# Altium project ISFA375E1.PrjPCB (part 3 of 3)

## Sheet ISFA375_REDRIVER_TUSB1044.SchDoc
size 431 x 279 mm; Date: Not shown in title block; ApprovedBy: Not shown in title block; CheckedBy: Not shown in title block; Author: Not shown in title block; CompanyName: Not shown in title block; DrawnBy: Thomas Mauer; Engineer: Not shown in title block; Organization: Not shown in title block; Address1: Not shown in title block; Address2: Not shown in title block; Address3: Not shown in title block; Address4: Not shown in title block; DocumentNumber: 6; Revision: Use project parameter SCH_Rev; SheetNumber: 6; SheetTotal: 11; PageSetup: Record=PageOptions¦CenterHorizontal=True¦CenterVertical=True¦PrintScale=1.00¦XCorrection=1.00¦YCorrection=1.00¦PrintKind=0¦BorderSize=5000000¦LeftOffset=0¦BottomOffset=0¦Orientation=2¦PaperLength=1000¦PaperWidth=1000¦Scale=100¦PaperSource=15¦PrintQuality=600¦MediaType=1¦DitherType=10¦PaperKind=Letter¦PrintScaleMode=1
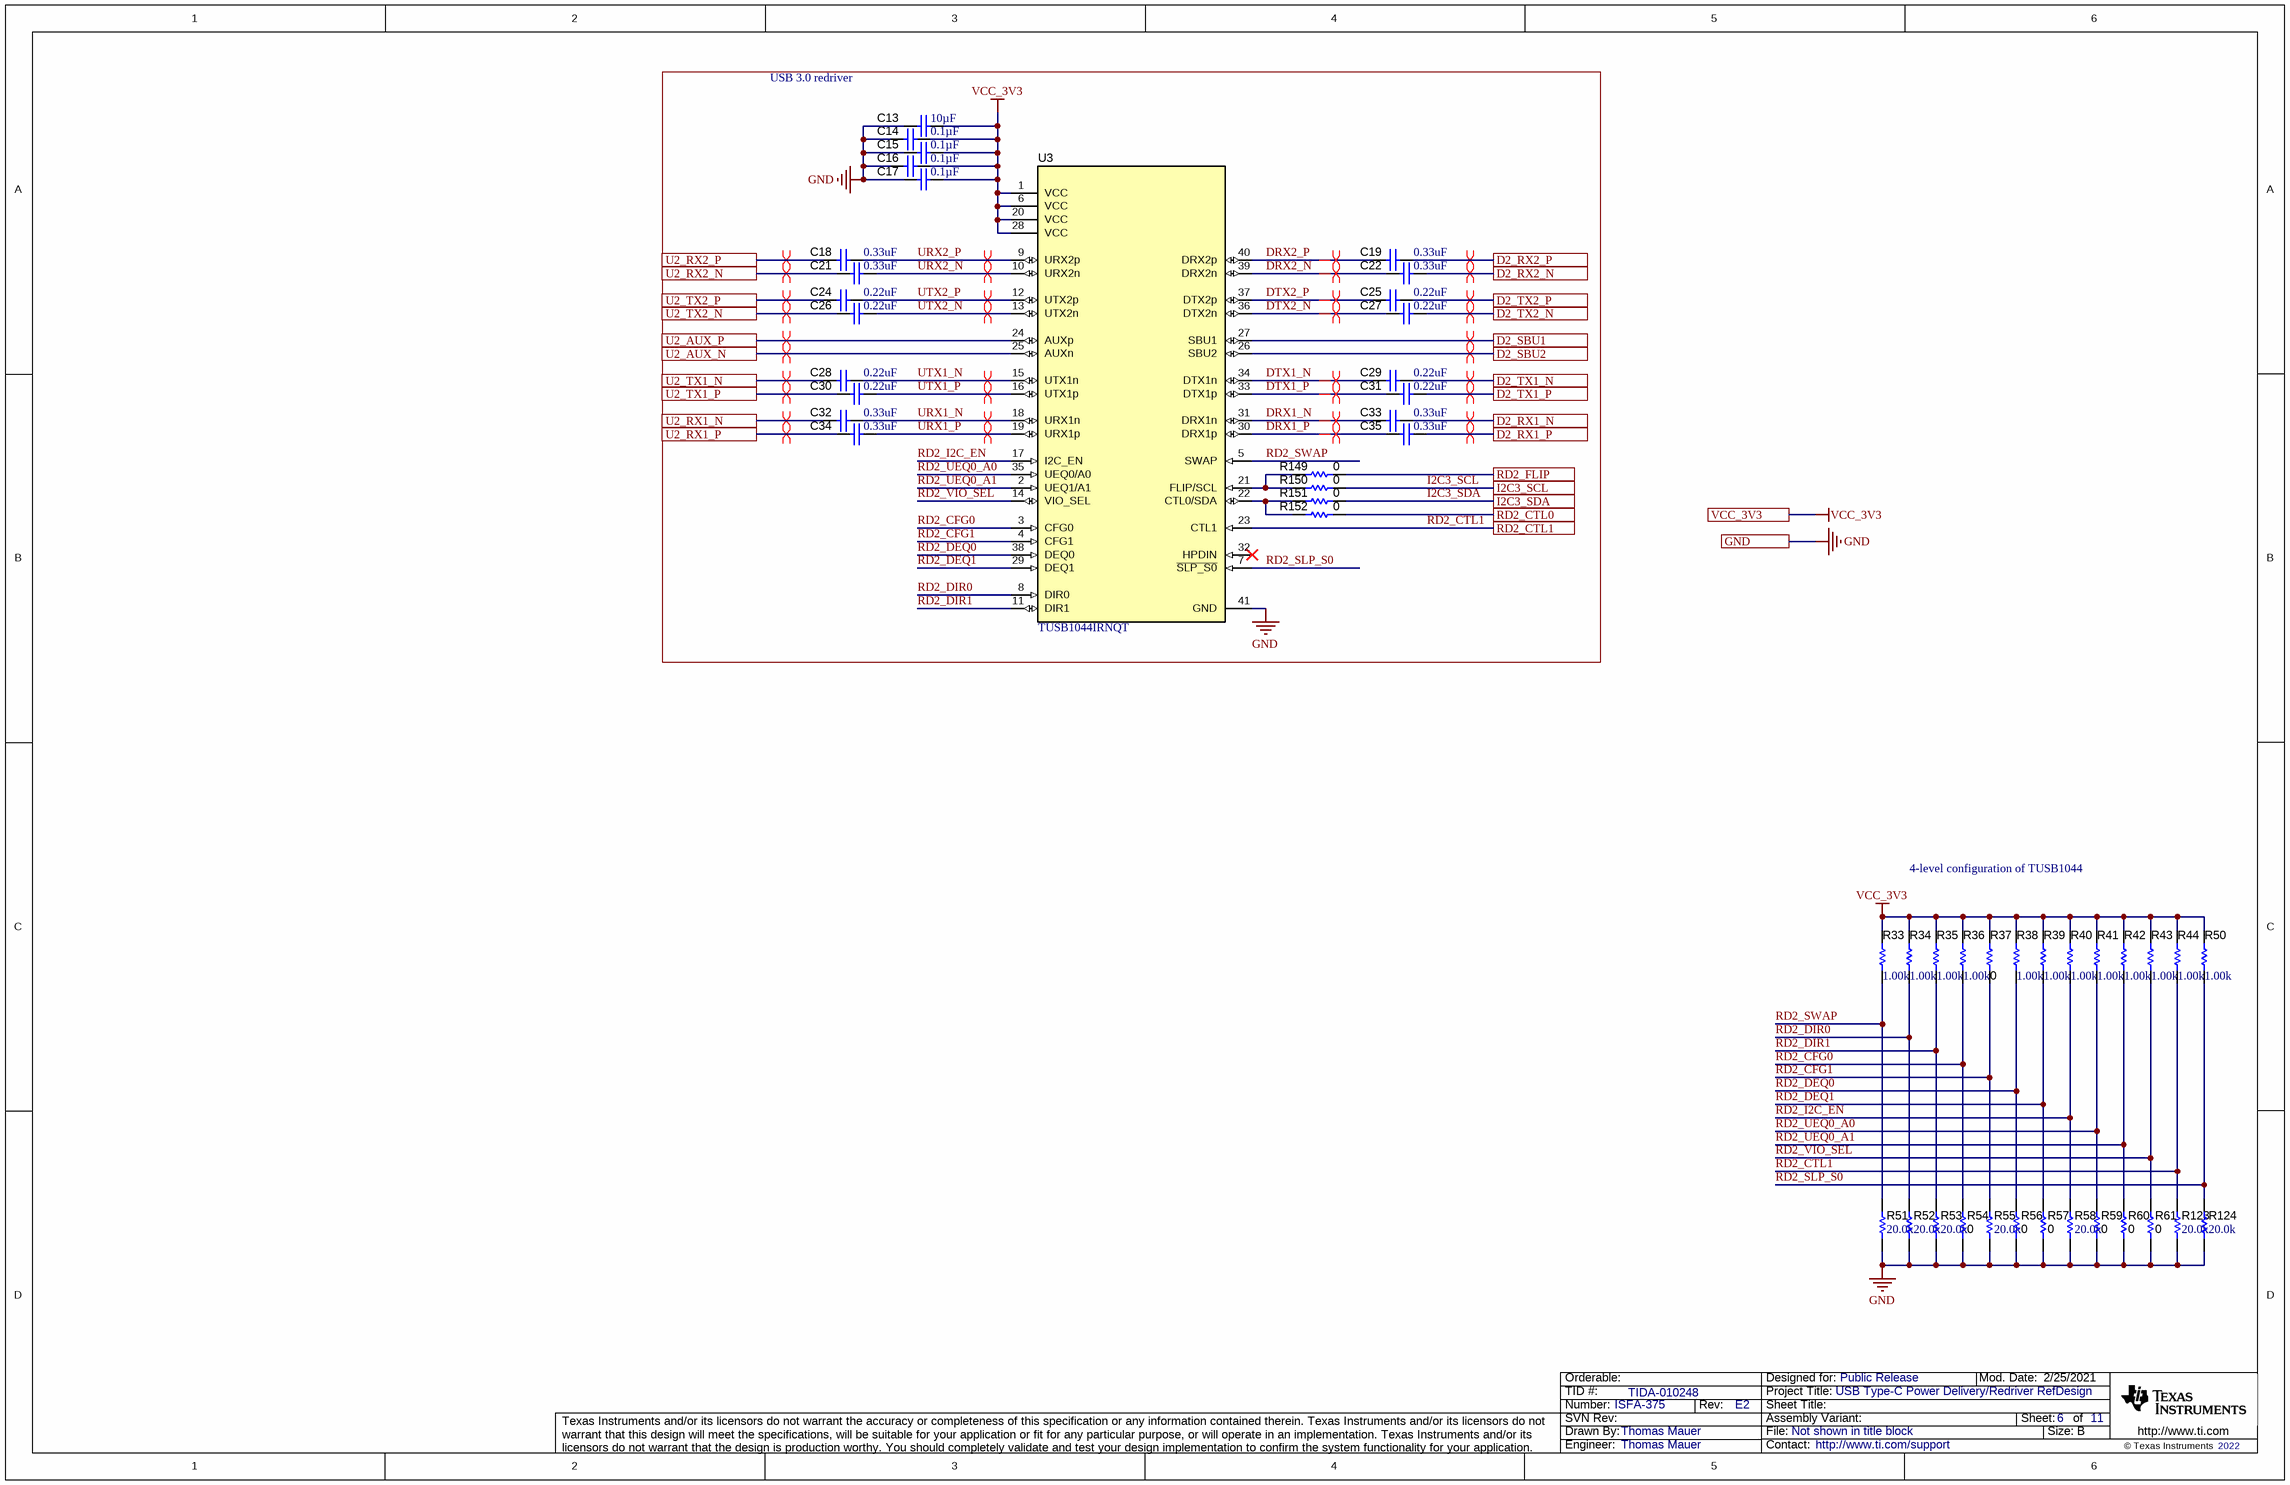
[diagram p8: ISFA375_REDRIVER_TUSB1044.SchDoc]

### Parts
C13  Cap_F: 10µF  [0805L]  (hidden comment: CL21B106KOQNNNE)
C14  ValueDisplayed: 0.1µF  [0201_033L]  (hidden comment: GRM033R61A104KE84D)
C15  ValueDisplayed: 0.1µF  [0201_033L]  (hidden comment: GRM033R61A104KE84D)
C16  ValueDisplayed: 0.1µF  [0201_033L]  (hidden comment: GRM033R61A104KE84D)
C17  ValueDisplayed: 0.1µF  [0201_033L]  (hidden comment: GRM033R61A104KE84D)
C18  ValueDisplayed: 0.33uF  [0201_033L]  (hidden comment: C0603X5R1A334K030BC)
C19  ValueDisplayed: 0.33uF  [0201_033L]  (hidden comment: C0603X5R1A334K030BC)
C21  ValueDisplayed: 0.33uF  [0201_033L]  (hidden comment: C0603X5R1A334K030BC)
C22  ValueDisplayed: 0.33uF  [0201_033L]  (hidden comment: C0603X5R1A334K030BC)
C24  ValueDisplayed: 0.22uF  [0201_033L]  (hidden comment: LMK063BJ224MP-F)
C25  ValueDisplayed: 0.22uF  [0201_033L]  (hidden comment: LMK063BJ224MP-F)
C26  ValueDisplayed: 0.22uF  [0201_033L]  (hidden comment: LMK063BJ224MP-F)
C27  ValueDisplayed: 0.22uF  [0201_033L]  (hidden comment: LMK063BJ224MP-F)
C28  ValueDisplayed: 0.22uF  [0201_033L]  (hidden comment: LMK063BJ224MP-F)
C29  ValueDisplayed: 0.22uF  [0201_033L]  (hidden comment: LMK063BJ224MP-F)
C30  ValueDisplayed: 0.22uF  [0201_033L]  (hidden comment: LMK063BJ224MP-F)
C31  ValueDisplayed: 0.22uF  [0201_033L]  (hidden comment: LMK063BJ224MP-F)
C32  ValueDisplayed: 0.33uF  [0201_033L]  (hidden comment: C0603X5R1A334K030BC)
C33  ValueDisplayed: 0.33uF  [0201_033L]  (hidden comment: C0603X5R1A334K030BC)
C34  ValueDisplayed: 0.33uF  [0201_033L]  (hidden comment: C0603X5R1A334K030BC)
C35  ValueDisplayed: 0.33uF  [0201_033L]  (hidden comment: C0603X5R1A334K030BC)
R33  ValueDisplayed: 1.00k  [0201L]  (hidden comment: CRCW02011K00FKED)
R34  ValueDisplayed: 1.00k  [0201L]  (hidden comment: CRCW02011K00FKED)
R35  ValueDisplayed: 1.00k  [0201L]  (hidden comment: CRCW02011K00FKED)
R36  ValueDisplayed: 1.00k  [0201L]  (hidden comment: CRCW02011K00FKED)
R37  ValueDisplayed: 0  [0201L]  (hidden comment: CRCW02010000Z0ED)
R38  ValueDisplayed: 1.00k  [0201L]  (hidden comment: CRCW02011K00FKED)
R39  ValueDisplayed: 1.00k  [0201L]  (hidden comment: CRCW02011K00FKED)
R40  ValueDisplayed: 1.00k  [0201L]  (hidden comment: CRCW02011K00FKED)
R41  ValueDisplayed: 1.00k  [0201L]  (hidden comment: CRCW02011K00FKED)
R42  ValueDisplayed: 1.00k  [0201L]  (hidden comment: CRCW02011K00FKED)
R43  ValueDisplayed: 1.00k  [0201L]  (hidden comment: CRCW02011K00FKED)
R44  ValueDisplayed: 1.00k  [0201L]  (hidden comment: CRCW02011K00FKED)
R50  ValueDisplayed: 1.00k  [0201L]  (hidden comment: CRCW02011K00FKED)
R51  ValueDisplayed: 20.0k  [0201L]  (hidden comment: CRCW020120K0FKED)
R52  ValueDisplayed: 20.0k  [0201L]  (hidden comment: CRCW020120K0FKED)
R53  ValueDisplayed: 20.0k  [0201L]  (hidden comment: CRCW020120K0FKED)
R54  ValueDisplayed: 0  [0201L]  (hidden comment: CRCW02010000Z0ED)
R55  ValueDisplayed: 20.0k  [0201L]  (hidden comment: CRCW020120K0FKED)
R56  ValueDisplayed: 0  [0201L]  (hidden comment: CRCW02010000Z0ED)
R57  ValueDisplayed: 0  [0201L]  (hidden comment: CRCW02010000Z0ED)
R58  ValueDisplayed: 20.0k  [0201L]  (hidden comment: CRCW020120K0FKED)
R59  ValueDisplayed: 0  [0201L]  (hidden comment: CRCW02010000Z0ED)
R60  ValueDisplayed: 0  [0201L]  (hidden comment: CRCW02010000Z0ED)
R61  ValueDisplayed: 0  [0201L]  (hidden comment: CRCW02010000Z0ED)
R123  ValueDisplayed: 20.0k  [0201L]  (hidden comment: CRCW020120K0FKED)
R124  ValueDisplayed: 20.0k  [0201L]  (hidden comment: CRCW020120K0FKED)
R149  ValueDisplayed: 0  [0201L]  (hidden comment: CRCW02010000Z0ED)
R150  ValueDisplayed: 0  [0201L]  (hidden comment: CRCW02010000Z0ED)
R151  ValueDisplayed: 0  [0201L]  (hidden comment: CRCW02010000Z0ED)
R152  ValueDisplayed: 0  [0201L]  (hidden comment: CRCW02010000Z0ED)
U3  TUSB1044IRNQT  [RNQ0040A]

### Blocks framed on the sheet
USB 3.0 redriver: C13-C19 C21 C22 C24-C35 R149-R152 U3

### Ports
D2_RX1_N, D2_RX1_P, D2_RX2_N, D2_RX2_P, D2_SBU1, D2_SBU2, D2_TX1_N, D2_TX1_P, D2_TX2_N, D2_TX2_P, GND, I2C3_SCL, I2C3_SDA, RD2_CTL0, RD2_CTL1, RD2_FLIP, U2_AUX_N, U2_AUX_P, U2_RX1_N, U2_RX1_P, U2_RX2_N, U2_RX2_P, U2_TX1_N, U2_TX1_P, U2_TX2_N, U2_TX2_P, VCC_3V3

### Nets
GND: C13.2 C14.2 C15.2 C16.2 C17.2 R51.1 R52.1 R53.1 R54.1 R55.1 R56.1 R57.1 R58.1 R59.1 R60.1 R61.1 R123.1 R124.1 U3.41(GND) ; port GND
VCC_3V3: C13.1 C14.1 C15.1 C16.1 C17.1 R33.2 R34.2 R35.2 R36.2 R37.2 R38.2 R39.2 R40.2 R41.2 R42.2 R43.2 R44.2 R50.2 U3.1(VCC) U3.6(VCC) U3.20(VCC) U3.28(VCC) ; port VCC_3V3  [project net VCC_3.3V]
AUX_N: U3.25(AUXn) ; port U2_AUX_N
AUX_N: U3.26(SBU2) ; port D2_SBU2  [a separate net that carries the same name]
AUX_P: U3.24(AUXp) ; port U2_AUX_P
AUX_P: U3.27(SBU1) ; port D2_SBU1  [a separate net that carries the same name]
D2_RX1_N: C33.1 ; port D2_RX1_N
D2_RX1_P: C35.1 ; port D2_RX1_P
D2_RX2_N: C22.1 ; port D2_RX2_N
D2_RX2_P: C19.1 ; port D2_RX2_P
D2_TX1_N: C29.1 ; port D2_TX1_N
D2_TX1_P: C31.1 ; port D2_TX1_P
D2_TX2_N: C27.1 ; port D2_TX2_N
D2_TX2_P: C25.1 ; port D2_TX2_P
DRX1_N: C33.2 U3.31(DRX1n)
DRX1_P: C35.2 U3.30(DRX1p)
DRX2_N: C22.2 U3.39(DRX2n)
DRX2_P: C19.2 U3.40(DRX2p)
DTX1_N: C29.2 U3.34(DTX1n)
DTX1_P: C31.2 U3.33(DTX1p)
DTX2_N: C27.2 U3.36(DTX2n)
DTX2_P: C25.2 U3.37(DTX2p)
I2C3_SCL: R150.2 ; port I2C3_SCL
I2C3_SDA: R151.2 ; port I2C3_SDA
RD2_CFG0: R36.1 R54.2 U3.3(CFG0)
RD2_CFG1: R37.1 R55.2 U3.4(CFG1)
RD2_CTL0: R152.2 ; port RD2_CTL0
RD2_CTL1: R44.1 R123.2 U3.23(CTL1) ; port RD2_CTL1
RD2_DEQ0: R38.1 R56.2 U3.38(DEQ0)
RD2_DEQ1: R39.1 R57.2 U3.29(DEQ1)
RD2_DIR0: R34.1 R52.2 U3.8(DIR0)
RD2_DIR1: R35.1 R53.2 U3.11(DIR1)
RD2_FLIP: R149.2 ; port RD2_FLIP
RD2_I2C_EN: R40.1 R58.2 U3.17(I2C_EN)
RD2_SLP_S0: R50.1 R124.2 U3.7(~{SLP_S0})
RD2_SWAP: R33.1 R51.2 U3.5(SWAP)
RD2_UEQ0_A0: R41.1 R59.2 U3.35(UEQ0/A0)
RD2_UEQ0_A1: R42.1 R60.2 U3.2(UEQ1/A1)
RD2_VIO_SEL: R43.1 R61.2 U3.14(VIO_SEL)
RX1_N: C32.2 ; port U2_RX1_N
RX1_P: C34.2 ; port U2_RX1_P
RX2_N: C21.2 ; port U2_RX2_N
RX2_P: C18.2 ; port U2_RX2_P
TX1_N: C28.2 ; port U2_TX1_N
TX1_P: C30.2 ; port U2_TX1_P
TX2_N: C26.2 ; port U2_TX2_N
TX2_P: C24.2 ; port U2_TX2_P
URX1_N: C32.1 U3.18(URX1n)
URX1_P: C34.1 U3.19(URX1p)
URX2_N: C21.1 U3.10(URX2n)
URX2_P: C18.1 U3.9(URX2p)
UTX1_N: C28.1 U3.15(UTX1n)
UTX1_P: C30.1 U3.16(UTX1p)
UTX2_N: C26.1 U3.13(UTX2n)
UTX2_P: C24.1 U3.12(UTX2p)
NetR149_1: R149.1 R150.1 U3.21(FLIP/SCL)
NetR151_1: R151.1 R152.1 U3.22(CTL0/SDA)

Not connected (* = marked no-connect by the designer): U3 32(HPDIN)*

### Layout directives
differential pair; net class Diff_pairs: AUX_N, AUX_P, D2_RX1_N, D2_RX1_P, D2_RX2_N, D2_RX2_P, D2_TX1_N, D2_TX1_P, D2_TX2_N, D2_TX2_P, DRX1_N, DRX1_P, DRX2_N, DRX2_P, DTX1_N, DTX1_P, DTX2_N, DTX2_P, RX1_N, RX1_P, RX2_N, RX2_P, TX1_N, TX1_P, TX2_N, TX2_P, URX1_N, URX1_P, URX2_N, URX2_P, UTX1_N, UTX1_P, UTX2_N, UTX2_P

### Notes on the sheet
- 4-level configuration of TUSB1044

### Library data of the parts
C13 = CMP-0007995-2: CAP, CERM, 10 uF, 16 V, +/- 10%, X7R, 0805; Manufacturer: Samsung Electro-Mechanics; TaMin_C: -55°C; Polarized: N; SizeAreaWB_mm2: 6.75; Value1: Unknown; U/M: EA; Value: 10uF; TaMax_C: 125°C; SizeZ_mm: 1.45; SizeX_mm: 2; SizeY_mm: 1.25; Cap_Case: 0805; Value2: 16V; SizeArea_mm2: 2.5; AEC Category: Q200
C14-C17 = CMP-0086059-1: CAP, CERM, 0.1 µF, 10 V,+/- 10%, X5R, 0201; Manufacturer: MuRata; AEC Category: Q200; Cap_F: 100nF; Value: 0.1uF; SizeY_mm: 0.3; AEC Qualified: N; SizeAreaWB_mm2: 2.08; Cap_Case: 0201; VDC_V: 10V; SizeArea_mm2: 0.18; SizeZ_mm: 0.33; SizeX_mm: 0.6; TaMax_C: 85°C; TaMin_C: -55°C; U/M: EA
C18 C19 C21 C22 C32-C35 = CMP-0009635-3: CAP, CERM, 0.33 uF, 10 V, +/- 10%, X5R, 0201; Manufacturer: TDK; TaMin_C: -55°C; Polarized: N; SizeAreaWB_mm2: 2.08; Value1: Unknown; U/M: EA; Value: 0.33uF; TaMax_C: 85°C; SizeZ_mm: 0.33; SizeX_mm: 0.6; SizeY_mm: 0.3; Cap_Case: 0201; Value2: 10V; SizeArea_mm2: 0.18; Cap_F: 330nF; AEC Category: Q200
C24-C31 = CMP-0009781-1: CAP, CERM, 0.22 uF, 10 V, +/- 20%, X5R, 0201; Manufacturer: Taiyo Yuden; TaMin_C: -55°C; Polarized: N; SizeAreaWB_mm2: 2.08; Value1: Unknown; U/M: EA; Value: 0.22uF; TaMax_C: 85°C; SizeZ_mm: 0.33; SizeX_mm: 0.6; SizeY_mm: 0.3; Cap_Case: 0201; Value2: 10V; SizeArea_mm2: 0.18; Cap_F: 220nF; AEC Category: Q200
R33-R36 R38-R44 R50 = CMP-0027267-3: RES, 1.00 k, 1%, 0.05 W, 0201; Manufacturer: Vishay-Dale; Power_W: 50mW; TempCo: 100 ppm/C; Value_Code: 1k00; Value: 1.00k; EIA_Code: E96; Res_ohm: 1k; SizeX_mm: 0.6; SizeY_mm: 0.3; SizeZ_mm: 0.26; Value2: 0.05W; SizeArea_mm2: 0.18; AEC Qualified: N; VDC_V: 30V; AEC Category: Q200
R37 R54 R56 R57 R59-R61 R149-R152 = CMP-0027008-4: RES, 0, 5%, 0.05 W, 0201; Manufacturer: Vishay-Dale; Power_W: 50mW; TempCo: ppm/C; Value_Code: 0000; Value: 0; EIA_Code: E24; SizeX_mm: 0.6; SizeY_mm: 0.3; SizeZ_mm: 0.26; Value2: 0.05W; SizeArea_mm2: 0.18; AEC Qualified: N; AEC Category: Q200
R51-R53 R55 R58 R123 R124 = CMP-0027269-3: RES, 20.0 k, 1%, 0.05 W, 0201; Manufacturer: Vishay-Dale; Power_W: 50mW; TempCo: 100 ppm/C; Value_Code: 20k0; Value: 20.0k; EIA_Code: E96; Res_ohm: 20k; SizeX_mm: 0.6; SizeY_mm: 0.3; SizeZ_mm: 0.26; Value2: 0.05W; SizeArea_mm2: 0.18; AEC Qualified: N; VDC_V: 30V; AEC Category: Q200
U3 = CMP-0082004-1: USB TYPE-C(TM) 10 Gbps Multi-Protocol Bi-Directional Linear Redriver, RNQ0040A (WQFN-40); Alternate PartNumber: TUSB1044IRNQR; Alternate Manufacturer: Texas Instruments; SizeAreaWB_mm2: 48; SizeZ_mm: 0.8; SizeX_mm: 6; SizeY_mm: 4; SizeArea_mm2: 24; CompType: IC; AEC Qualified: N; AEC Category: Q200

## Sheet ISFA375_Hardware.SchDoc
size 431 x 279 mm; Date: Not shown in title block; ApprovedBy: Not shown in title block; CheckedBy: Not shown in title block; Author: Not shown in title block; CompanyName: Not shown in title block; DrawnBy: Thomas Mauer; Engineer: Not shown in title block; Organization: Not shown in title block; Address1: Not shown in title block; Address2: Not shown in title block; Address3: Not shown in title block; Address4: Not shown in title block; DocumentNumber: 11; Revision: Use project parameter SCH_Rev; SheetNumber: 11; SheetTotal: 11; PageSetup: Record=PageOptions¦CenterHorizontal=True¦CenterVertical=True¦PrintScale=1.00¦XCorrection=1.00¦YCorrection=1.00¦PrintKind=0¦BorderSize=5000000¦LeftOffset=0¦BottomOffset=0¦Orientation=2¦PaperLength=1000¦PaperWidth=1000¦Scale=100¦PaperSource=15¦PrintQuality=600¦MediaType=1¦DitherType=10¦PaperKind=Letter¦PrintScaleMode=1
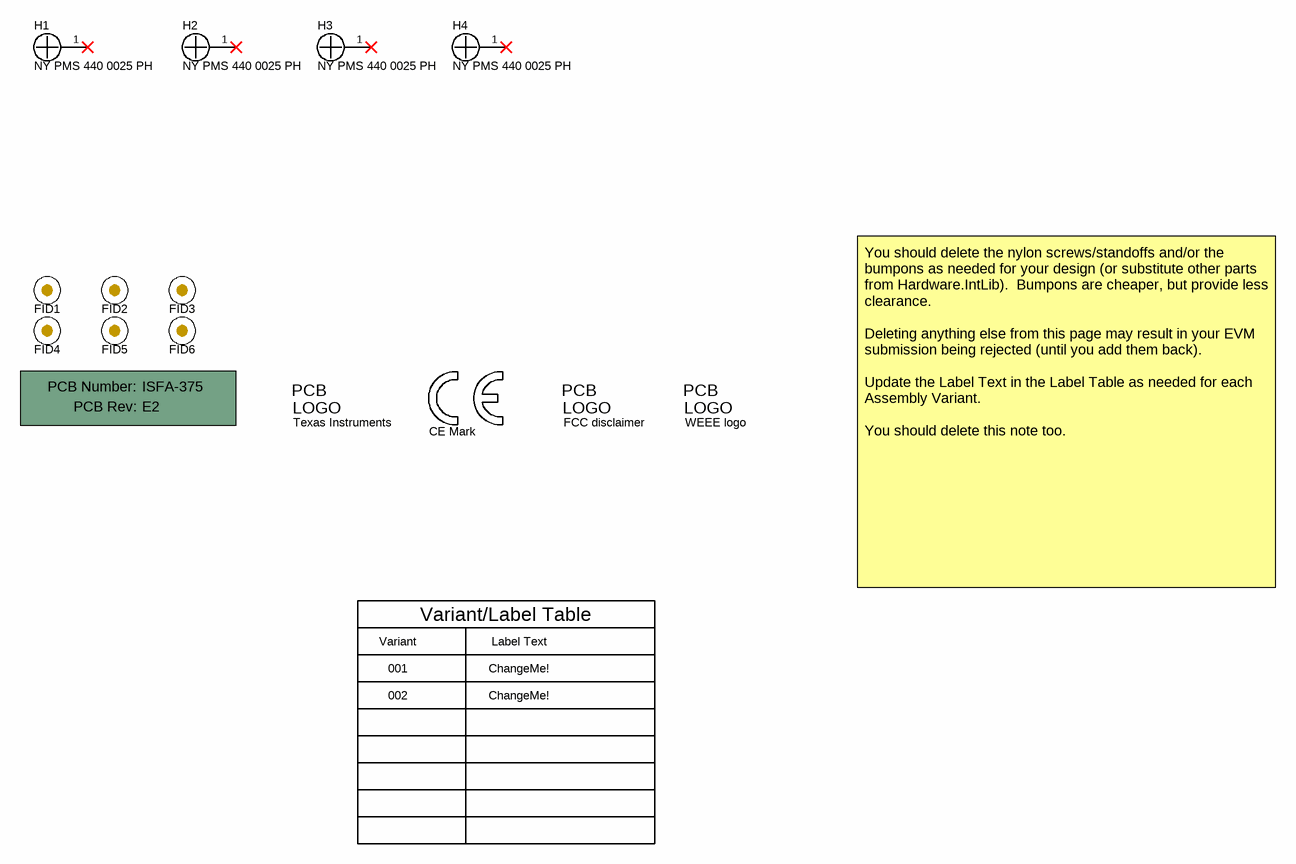
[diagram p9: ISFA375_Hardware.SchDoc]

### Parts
!PCB  Printed Circuit Board  (value not drawn)  (mechanical)
FID1  Fiducial  [Fiducial10-20]  (value not drawn)
FID2  Fiducial  [Fiducial10-20]  (value not drawn)
FID3  Fiducial  [Fiducial10-20]  (value not drawn)
FID4  Fiducial  [Fiducial10-20]  (value not drawn)
FID5  Fiducial  [Fiducial10-20]  (value not drawn)
FID6  Fiducial  [Fiducial10-20]  (value not drawn)
H1  NY PMS 440 0025 PH  [NY PMS 440 0025 PH]
H2  NY PMS 440 0025 PH  [NY PMS 440 0025 PH]
H3  NY PMS 440 0025 PH  [NY PMS 440 0025 PH]
H4  NY PMS 440 0025 PH  [NY PMS 440 0025 PH]
Logo1  Texas Instruments  [TI_Stacked_Overlay_Small]  (no BOM)
Logo2  CE Mark  [CE_Mark_5mm]  (no BOM)
Logo4  WEEE logo  [WEEE_Minimum]  (no BOM)
Logo100  FCC disclaimer  [FCC_disclaimer]  (no BOM)

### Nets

Not connected (* = marked no-connect by the designer): H1 1*; H2 1*; H3 1*; H4 1*

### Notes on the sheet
- Variant
- Variant/Label Table
- Label Text
- You should delete the nylon screws/standoffs and/or the bumpons as needed for your design (or substitute other parts from Hardware.IntLib).  Bumpons are cheaper, but provide less clearance.
  Deleting anything else from this page may result in your EVM submission being rejected (until you add them back).
  Update the Label Text in the Label Table as needed for each Assembly Variant.
  You should delete this note too.
- 001
- 002
- ChangeMe!

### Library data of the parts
!PCB = CMP-0003618-2: Manufacturer: Any; PartNumber: ISFA-375
FID1-FID6 = CMP-0077181-1: Fiducial mark.  There is nothing to buy or mount.
H1-H4 = CMP-0003617-1: Machine Screw, Round, #4-40 x 1/4, Nylon, Philips panhead; Manufacturer: B&F Fastener Supply; CompType: Hardware
Logo1 = CMP-0074838-1: Texas Instrument Corporate Signature; SymbolCreator: a0412235; Lib Reference: TI_Logo; Library Reference: Logo
Logo2 = CMP-0074844-1: SymbolCreator: a0412235
Logo4 = CMP-0074769-1
Logo100 = CMP-0074847-1: FCC_disclaimer; Library Reference: Logo

## Sheet ISFA375_US_Sideband_Interface.SchDoc
size 431 x 279 mm; Date: Not shown in title block; ApprovedBy: Not shown in title block; CheckedBy: Not shown in title block; Author: Not shown in title block; CompanyName: Not shown in title block; DrawnBy: Thomas Mauer; Engineer: Not shown in title block; Organization: Not shown in title block; Address1: Not shown in title block; Address2: Not shown in title block; Address3: Not shown in title block; Address4: Not shown in title block; DocumentNumber: 5; Revision: Use project parameter SCH_Rev; SheetNumber: 5; SheetTotal: 11; PageSetup: Record=PageOptions¦CenterHorizontal=True¦CenterVertical=True¦PrintScale=1.00¦XCorrection=1.00¦YCorrection=1.00¦PrintKind=0¦BorderSize=5000000¦LeftOffset=0¦BottomOffset=0¦Orientation=2¦PaperLength=1000¦PaperWidth=1000¦Scale=100¦PaperSource=15¦PrintQuality=600¦MediaType=1¦DitherType=10¦PaperKind=Letter¦PrintScaleMode=1
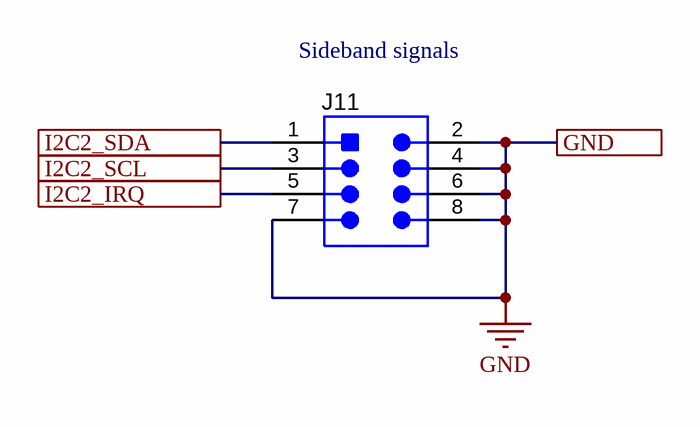
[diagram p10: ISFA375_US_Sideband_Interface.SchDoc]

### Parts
J11  61000821121  [Wurth_61000821121]  (value not drawn)

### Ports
GND, I2C2_IRQ, I2C2_SCL, I2C2_SDA

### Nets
GND: J11.2 J11.4 J11.6 J11.7 J11.8 ; port GND
I2C2_IRQ: J11.5 ; port I2C2_IRQ
I2C2_SCL: J11.3 ; port I2C2_SCL
I2C2_SDA: J11.1 ; port I2C2_SDA

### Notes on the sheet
- (near J11) Sideband signals

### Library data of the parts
J11 = CMP-0079535-2: Header, 2.54mm, 4x2, Gold, SMT; Manufacturer: Wurth Elektronik; Pitch_mm: 2.54; Gender: Male; Cert_UL: Y; Current_A: 3A; Voltage_V: 250V; Shrouded: N; Row_Count: 2

## Sheet ISFA375_REDRIVER_TUSB216I.SchDoc
size 431 x 279 mm; Date: Not shown in title block; ApprovedBy: Not shown in title block; CheckedBy: Not shown in title block; Author: Not shown in title block; CompanyName: Not shown in title block; DrawnBy: Thomas Mauer; Engineer: Not shown in title block; Organization: Not shown in title block; Address1: Not shown in title block; Address2: Not shown in title block; Address3: Not shown in title block; Address4: Not shown in title block; DocumentNumber: 3; Revision: Use project parameter SCH_Rev; SheetNumber: 3; SheetTotal: 11; PageSetup: Record=PageOptions¦CenterHorizontal=True¦CenterVertical=True¦PrintScale=1.00¦XCorrection=1.00¦YCorrection=1.00¦PrintKind=0¦BorderSize=5000000¦LeftOffset=0¦BottomOffset=0¦Orientation=2¦PaperLength=1000¦PaperWidth=1000¦Scale=100¦PaperSource=15¦PrintQuality=600¦MediaType=1¦DitherType=10¦PaperKind=Letter¦PrintScaleMode=1
Used 2 times, as channels USB1, USB2. Parts and nets are listed once, with the designators drawn on the sheet.
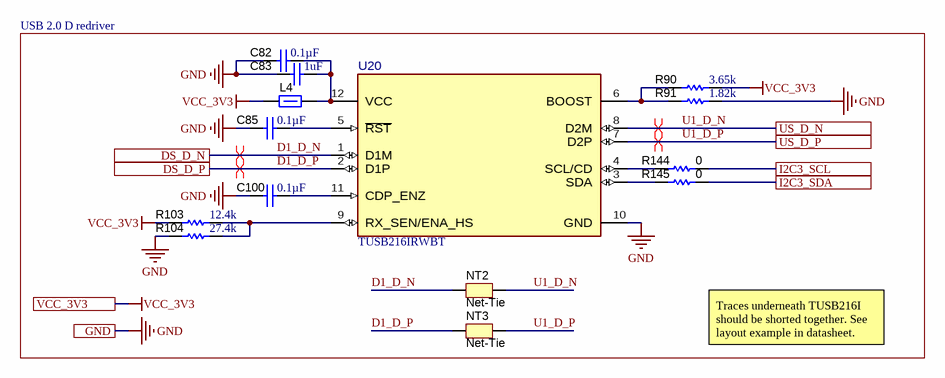
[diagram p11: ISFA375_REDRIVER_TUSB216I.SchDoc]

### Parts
C82  ValueDisplayed: 0.1µF  [0201_033L]  (hidden comment: GRM033R61A104KE84D)
C83  ValueDisplayed: 1uF  [0603L]  (hidden comment: C0603C105K4PACTU)
C85  ValueDisplayed: 0.1µF  [0201_033L]  (hidden comment: GRM033R61A104KE84D)
C100  ValueDisplayed: 0.1µF  [0201_033L]  (hidden comment: GRM033R61A104KE84D)
L4  74279207  [0805L]  (value not drawn)
NT2  Net-Tie  [Net-Tie_6x8mil]  (net tie, no BOM)
NT3  Net-Tie  [Net-Tie_6x8mil]  (net tie, no BOM)
R90  ValueDisplayed: 3.65k  [0201L]  (hidden comment: RC0201FR-073K65L)
R91  ValueDisplayed: 1.82k  [0201L]  (hidden comment: RC0201FR-071K82L)
R103  ValueDisplayed: 12.4k  [0201L]  (hidden comment: RC0201FR-0712K4L)
R104  ValueDisplayed: 27.4k  [0201L]  (hidden comment: RC0201FR-0727K4L)
R144  ValueDisplayed: 0  [0201L]  (hidden comment: CRCW02010000Z0ED)
R145  ValueDisplayed: 0  [0201L]  (hidden comment: CRCW02010000Z0ED)
U20  TUSB216IRWBT  [RWB0012A-MFG]

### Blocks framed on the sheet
USB 2.0 D redriver: C82 C83 C85 C100 L4 NT2 NT3 R90 R91 R103 R104 R144 R145 U20

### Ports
DS_D_N, DS_D_P, GND, I2C3_SCL, I2C3_SDA, US_D_N, US_D_P, VCC_3V3

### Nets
GND: C82.2 C83.2 C85.2 C100.2 R91.2 R104.1 U20.10(GND) ; port GND
VCC_3V3: L4.1 R90.2 R103.1 ; port VCC_3V3
D1_D_N: NT2.1 U20.1(D1M) ; port DS_D_N
D1_D_P: NT3.1 U20.2(D1P) ; port DS_D_P
I2C3_SCL: R144.2 ; port I2C3_SCL
I2C3_SDA: R145.2 ; port I2C3_SDA
U1_D_N: NT2.2 U20.8(D2M) ; port US_D_N
U1_D_P: NT3.2 U20.7(D2P) ; port US_D_P
NetC82_1: C82.1 C83.1 L4.2 U20.12(VCC)
NetC85_1: C85.1 U20.5(~{RST})
NetC100_1: C100.1 U20.11(CDP_ENZ)
NetR90_1: R90.1 R91.1 U20.6(BOOST)
NetR103_2: R103.2 R104.2 U20.9(RX_SEN/ENA_HS)
NetR144_1: R144.1 U20.4(SCL/CD)
NetR145_1: R145.1 U20.3(SDA)

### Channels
USB1: designators end in _USB1; ports DS_D_N=D1_D_N DS_D_P=D1_D_P GND=GND I2C3_SCL=I2C3_SCL I2C3_SDA=I2C3_SDA US_D_N=D_N US_D_P=D_P VCC_3V3=VCC_3.3V
USB2: designators end in _USB2; ports DS_D_N=D1_D_N DS_D_P=D1_D_P GND=GND I2C3_SCL=I2C3_SCL I2C3_SDA=I2C3_SDA US_D_N=D_N US_D_P=D_P VCC_3V3=VCC_3.3V

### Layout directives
differential pair; net class Diff_pairs: D1_D_N, D1_D_P, D_N, D_P

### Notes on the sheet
- Traces underneath TUSB216I should be shorted together. See layout example in datasheet.

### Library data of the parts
C82 C85 C100 = CMP-0086059-1: as C14-C17 on sheet ISFA375_REDRIVER_TUSB1044
C83 = CMP-0006868-5: CAP, CERM, 1 uF, 16 V, +/- 10%, X5R, 0603; Manufacturer: Kemet; TaMin_C: -55°C; Polarized: N; SizeAreaWB_mm2: 4.68; Value1: Unknown; U/M: EA; Value: 1uF; TaMax_C: 85°C; SizeZ_mm: 1; SizeX_mm: 1.6; SizeY_mm: 0.8; Cap_Case: 0603; Value2: 16V; SizeArea_mm2: 1.28; Cap_F: 1µF; AEC Category: Q200
L4 = CMP-0003095-1: Ferrite Bead, 100 ohm @ 100 MHz, 1 A, 0805; Manufacturer: Wurth Elektronik; Ztyp@1GHz_Ohm: 200.151; ZTyp@100MHz_Ohm: 100; SizeAreaWB_mm2: 6.75; DCR_ohm: 1.5d; Value1: 0.15 ohm; Value: 100 ohm; Imax_A: 1A; SizeZ_mm: 1.45; SizeX_mm: 2; SizeY_mm: 1.25; SizeArea_mm2: 2.5
NT2 NT3 = CMP-0078142-4: Single point connection between nets.
R90 = CMP-0027661-1: RES, 3.65 k, 1%, 0.05 W, 0201; Manufacturer: Yageo America; Power_W: 50mW; TempCo: 200 ppm/C; Value_Code: 3k65; U/M: EA; Value: 3.65k; EIA_Code: E96; SizeX_mm: 0.6; SizeY_mm: 0.3; SizeZ_mm: 0.26; Value2: 0.05W; SizeArea_mm2: 0.18; AEC Qualified: N; VDC_V: 25V; AEC Category: Q200
R91 = CMP-0027448-1: RES, 1.82 k, 1%, 0.05 W, 0201; Manufacturer: Yageo America; Power_W: 50mW; TempCo: 200 ppm/C; Value_Code: 1k82; U/M: EA; Value: 1.82k; EIA_Code: E96; SizeX_mm: 0.6; SizeY_mm: 0.3; SizeZ_mm: 0.26; Value2: 0.05W; SizeArea_mm2: 0.18; AEC Qualified: N; VDC_V: 25V; AEC Category: Q200
R103 = CMP-0027335-2: RES, 12.4 k, 1%, 0.05 W, 0201; Manufacturer: Yageo America; Power_W: 50mW; TempCo: 200 ppm/C; Value_Code: 12k4; U/M: EA; Value: 12.4k; EIA_Code: E96; SizeX_mm: 0.6; SizeY_mm: 0.3; SizeZ_mm: 0.26; Value2: 0.05W; SizeArea_mm2: 0.18; AEC Qualified: N; VDC_V: 25V; AEC Category: Q200
R104 = CMP-0027537-1: RES, 27.4 k, 1%, 0.05 W, 0201; Manufacturer: Yageo America; Power_W: 50mW; TempCo: 200 ppm/C; Value_Code: 27k4; U/M: EA; Value: 27.4k; EIA_Code: E96; SizeX_mm: 0.6; SizeY_mm: 0.3; SizeZ_mm: 0.26; Value2: 0.05W; SizeArea_mm2: 0.18; AEC Qualified: N; VDC_V: 25V; AEC Category: Q200
R144 R145 = CMP-0027008-4: as R37 on sheet ISFA375_REDRIVER_TUSB1044
U20 = CMP-0093449-1: USB 2.0 high-speed signal conditioner with BC 1.2 controller 12-X2QFN -40 to 85; Manufacturer: Texas Instruments; Standoff Height: 0mm; SizeZ_mm: 0.4mm; Data Rate: 480Mbits/s; TJmax_C: +105°C; TaMin_C: -40°C; AEC Qualified: No; Usb Standard: USB 2.0; Interface: I2C,USB; Nominal Supply Current: 0.75-22mA; TaMax_C: +85°C; Min Supply Voltage: 2.3V; Max Supply Voltage: 6.5V

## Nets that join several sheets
GND: US1 (24 pins), ISFA375_PD_TPS65994 (51 pins), ISFA375_DEBUG_MCU_TIVA (39 pins), DS1 (31 pins), ISFA375_SYSTEM_POWER (32 pins), V1 (19 pins), V2 (19 pins), ISFA375_REDRIVER_TUSB1104 (16 pins), ISFA375_REDRIVER_TUSB1044 (19 pins), ISFA375_US_Sideband_Interface (5 pins), USB1 (7 pins), USB2 (7 pins), US2 (24 pins), DS2 (31 pins)
VCC_3.3V: ISFA375_PD_TPS65994 (C4.1 U1.32), ISFA375_DEBUG_MCU_TIVA (16 pins), DS1 (C122_DS1.1 R163_DS1.1 U23_DS1.10), ISFA375_SYSTEM_POWER (7 pins), ISFA375_REDRIVER_TUSB1104 (19 pins), ISFA375_REDRIVER_TUSB1044 (22 pins), USB1 (L4_USB1.1 R90_USB1.2 R103_USB1.1), USB2 (L4_USB2.1 R90_USB2.2 R103_USB2.1), DS2 (C122_DS2.1 R163_DS2.1 U23_DS2.10)
VCC_5V: ISFA375_PD_TPS65994 (11 pins), ISFA375_SYSTEM_POWER (8 pins)
VCC_IN: ISFA375_SYSTEM_POWER (18 pins), V1 (12 pins), V2 (12 pins)
AUX_N: US1 (J8_US1.B8 U4_US1.2), ISFA375_REDRIVER_TUSB1104 (NT5.1)
AUX_N: DS1 (U23_DS1.14), ISFA375_REDRIVER_TUSB1104 (NT5.2)
AUX_N: ISFA375_REDRIVER_TUSB1044 (U3.25), US2 (J8_US2.B8 U4_US2.2)
AUX_N: ISFA375_REDRIVER_TUSB1044 (U3.26), DS2 (U23_DS2.14)
AUX_P: US1 (J8_US1.A8 U4_US1.3), ISFA375_REDRIVER_TUSB1104 (NT4.1)
AUX_P: DS1 (U23_DS1.15), ISFA375_REDRIVER_TUSB1104 (NT4.2)
AUX_P: ISFA375_REDRIVER_TUSB1044 (U3.24), US2 (J8_US2.A8 U4_US2.3)
AUX_P: ISFA375_REDRIVER_TUSB1044 (U3.27), DS2 (U23_DS2.15)
D1_D_N: DS1 (J9_DS1.A7 J9_DS1.B7 U23_DS1.20), USB1 (NT2_USB1.1 U20_USB1.1)
D1_D_N: USB2 (NT2_USB2.1 U20_USB2.1), DS2 (J9_DS2.A7 J9_DS2.B7 U23_DS2.20)
D1_D_P: DS1 (J9_DS1.A6 J9_DS1.B6 U23_DS1.19), USB1 (NT3_USB1.1 U20_USB1.2)
D1_D_P: USB2 (NT3_USB2.1 U20_USB2.2), DS2 (J9_DS2.A6 J9_DS2.B6 U23_DS2.19)
D1_RX1_N: DS1 (J9_DS1.B10 U9_DS1.2), ISFA375_REDRIVER_TUSB1104 (C73.1)
D1_RX1_P: DS1 (J9_DS1.B11 U9_DS1.3), ISFA375_REDRIVER_TUSB1104 (C75.1)
D1_RX2_N: DS1 (J9_DS1.A10 U6_DS1.2), ISFA375_REDRIVER_TUSB1104 (C39.1)
D1_RX2_P: DS1 (J9_DS1.A11 U6_DS1.3), ISFA375_REDRIVER_TUSB1104 (C38.1)
D1_TX1_N: DS1 (J9_DS1.A3 U8_DS1.3), ISFA375_REDRIVER_TUSB1104 (C74.1)
D1_TX1_P: DS1 (J9_DS1.A2 U8_DS1.2), ISFA375_REDRIVER_TUSB1104 (C72.1)
D1_TX2_N: DS1 (J9_DS1.B3 U7_DS1.3), ISFA375_REDRIVER_TUSB1104 (C67.1)
D1_TX2_P: DS1 (J9_DS1.B2 U7_DS1.2), ISFA375_REDRIVER_TUSB1104 (C64.1)
D2_RX1_N: ISFA375_REDRIVER_TUSB1044 (C33.1), DS2 (J9_DS2.B10 U9_DS2.2)
D2_RX1_P: ISFA375_REDRIVER_TUSB1044 (C35.1), DS2 (J9_DS2.B11 U9_DS2.3)
D2_RX2_N: ISFA375_REDRIVER_TUSB1044 (C22.1), DS2 (J9_DS2.A10 U6_DS2.2)
D2_RX2_P: ISFA375_REDRIVER_TUSB1044 (C19.1), DS2 (J9_DS2.A11 U6_DS2.3)
D2_TX1_N: ISFA375_REDRIVER_TUSB1044 (C29.1), DS2 (J9_DS2.A3 U8_DS2.3)
D2_TX1_P: ISFA375_REDRIVER_TUSB1044 (C31.1), DS2 (J9_DS2.A2 U8_DS2.2)
D2_TX2_N: ISFA375_REDRIVER_TUSB1044 (C27.1), DS2 (J9_DS2.B3 U7_DS2.3)
D2_TX2_P: ISFA375_REDRIVER_TUSB1044 (C25.1), DS2 (J9_DS2.B2 U7_DS2.2)
D_N: US1 (J8_US1.A7 J8_US1.B7 U16_US1.2), USB1 (NT2_USB1.2 U20_USB1.8)
D_N: USB2 (NT2_USB2.2 U20_USB2.8), US2 (J8_US2.A7 J8_US2.B7 U16_US2.2)
D_P: US1 (J8_US1.A6 J8_US1.B6 U16_US1.3), USB1 (NT3_USB1.2 U20_USB1.7)
D_P: USB2 (NT3_USB2.2 U20_USB2.7), US2 (J8_US2.A6 J8_US2.B6 U16_US2.3)
I2C1_SCL: ISFA375_PD_TPS65994 (R3.2 U1.42), ISFA375_DEBUG_MCU_TIVA (R30.1 U11.2)
I2C1_SDA: ISFA375_PD_TPS65994 (R4.2 U1.40), ISFA375_DEBUG_MCU_TIVA (R46.1 U11.1)
I2C2_IRQ: ISFA375_PD_TPS65994 (R8.2 U1.39), ISFA375_US_Sideband_Interface (J11.5)
I2C2_SCL: ISFA375_PD_TPS65994 (R6.2 U1.41), ISFA375_DEBUG_MCU_TIVA (R45.2), ISFA375_US_Sideband_Interface (J11.3)
I2C2_SDA: ISFA375_PD_TPS65994 (R7.2 U1.44), ISFA375_DEBUG_MCU_TIVA (R47.2), ISFA375_US_Sideband_Interface (J11.1)
I2C3_SCL: ISFA375_PD_TPS65994 (R9.2 R108.1 U2.6), ISFA375_DEBUG_MCU_TIVA (U11.4), V1 (U18_V1.5), V2 (U18_V2.5), ISFA375_REDRIVER_TUSB1104 (R154.2), ISFA375_REDRIVER_TUSB1044 (R150.2), USB1 (R144_USB1.2), USB2 (R144_USB2.2)
I2C3_SDA: ISFA375_PD_TPS65994 (R10.2 R109.1 U2.5), ISFA375_DEBUG_MCU_TIVA (U11.3), V1 (U18_V1.6), V2 (U18_V2.6), ISFA375_REDRIVER_TUSB1104 (U19.22), ISFA375_REDRIVER_TUSB1044 (R151.2), USB1 (R145_USB1.2), USB2 (R145_USB2.2)
PA_CC1: ISFA375_PD_TPS65994 (C1.2 TP1.1 U1.31), DS1 (R159_DS1.1)
PA_CC2: ISFA375_PD_TPS65994 (C2.2 TP2.1 U1.30), DS1 (R160_DS1.1)
PA_PPHV: ISFA375_PD_TPS65994 (R105.2 U10.5), V1 (C52_V1.1 R69_V1.2 R77_V1.2 TP7_V1.1)
PA_VBUS: ISFA375_PD_TPS65994 (9 pins), DS1 (L2_DS1.1)
PB_CC1: ISFA375_PD_TPS65994 (C6.1 TP4.1 U1.6), DS2 (R159_DS2.1)
PB_CC2: ISFA375_PD_TPS65994 (C7.1 TP5.1 U1.7), DS2 (R160_DS2.1)
PB_PPHV: ISFA375_PD_TPS65994 (R168.2 U25.5), V2 (C52_V2.1 R69_V2.2 R77_V2.2 TP7_V2.1)
PB_VBUS: ISFA375_PD_TPS65994 (9 pins), DS2 (L2_DS2.1)
RD1_EN: ISFA375_PD_TPS65994 (R135.1), ISFA375_REDRIVER_TUSB1104 (R140.2)
RD1_FLIP: ISFA375_PD_TPS65994 (R128.1), ISFA375_REDRIVER_TUSB1104 (R153.2)
RD2_CTL0: ISFA375_PD_TPS65994 (R129.1), ISFA375_REDRIVER_TUSB1044 (R152.2)
RD2_CTL1: ISFA375_PD_TPS65994 (R147.1), ISFA375_REDRIVER_TUSB1044 (R44.1 R123.2 U3.23)
RD2_FLIP: ISFA375_PD_TPS65994 (R148.1), ISFA375_REDRIVER_TUSB1044 (R149.2)
RX1_N: US1 (J8_US1.B10 U15_US1.3), ISFA375_REDRIVER_TUSB1104 (C76.2)
RX1_N: ISFA375_REDRIVER_TUSB1044 (C32.2), US2 (J8_US2.B10 U15_US2.3)
RX1_P: US1 (J8_US1.B11 U15_US1.2), ISFA375_REDRIVER_TUSB1104 (C77.2)
RX1_P: ISFA375_REDRIVER_TUSB1044 (C34.2), US2 (J8_US2.B11 U15_US2.2)
RX2_N: US1 (J8_US1.A10 U12_US1.3), ISFA375_REDRIVER_TUSB1104 (C69.2)
RX2_N: ISFA375_REDRIVER_TUSB1044 (C21.2), US2 (J8_US2.A10 U12_US2.3)
RX2_P: US1 (J8_US1.A11 U12_US1.2), ISFA375_REDRIVER_TUSB1104 (C68.2)
RX2_P: ISFA375_REDRIVER_TUSB1044 (C18.2), US2 (J8_US2.A11 U12_US2.2)
TX1_N: US1 (J8_US1.A3 U14_US1.2), ISFA375_REDRIVER_TUSB1104 (C78.2)
TX1_N: ISFA375_REDRIVER_TUSB1044 (C28.2), US2 (J8_US2.A3 U14_US2.2)
TX1_P: US1 (J8_US1.A2 U14_US1.3), ISFA375_REDRIVER_TUSB1104 (C79.2)
TX1_P: ISFA375_REDRIVER_TUSB1044 (C30.2), US2 (J8_US2.A2 U14_US2.3)
TX2_N: US1 (J8_US1.B3 U13_US1.2), ISFA375_REDRIVER_TUSB1104 (C71.2)
TX2_N: ISFA375_REDRIVER_TUSB1044 (C26.2), US2 (J8_US2.B3 U13_US2.2)
TX2_P: US1 (J8_US1.B2 U13_US1.3), ISFA375_REDRIVER_TUSB1104 (C70.2)
TX2_P: ISFA375_REDRIVER_TUSB1044 (C24.2), US2 (J8_US2.B2 U13_US2.3)

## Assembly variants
001: not fitted C129 C130 C131 FID1 FID2 FID3 R12 R17 R18 R19 R21 R29 R30 R31 R32 R33 R36 R38 R39 R41 R42 R43 R44 R45 R46 R51 R55 R58 R79 R80 R81 R82 R83 R84 R85 R86 R87 R93 R94 R95 R96 R97 R98 R99 R100 R101 R123 R124 R128 R129 R133 R137 R138 R144_USB1 R144_USB2 R145_USB1 R145_USB2 R146 R147 R148 R149 R152 R153 R164 R172 TP7_V1 TP8_V1 TP9_US1 TP9_US2 TP10_DS1 TP10_DS2 TP12 TP19 U4_US1 U4_US2 U12_US1 U12_US2 U13_US1 U13_US2 U14_US1 U14_US2 U15_US1 U15_US2 U16_US1 U16_US2; alternate parts R54 -> CMP-0027008-4, R37 -> CMP-0027269-3, R56 -> CMP-0027008-4, R57 -> CMP-0027008-4, R59 -> CMP-0027008-4, R60 -> CMP-0027008-4, R61 -> CMP-0027008-4, R75_V2 -> CMP-0027986-1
